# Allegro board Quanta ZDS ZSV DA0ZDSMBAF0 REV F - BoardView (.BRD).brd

Outline 275.3 x 62 mm; copper layers: TOP, IN1, GND1, IN2, SGND, SVCC, IN3, GND2, IN4, BOTTOM. Coordinates in mm from the lower left corner of the outline.
Outline path: 0,24.6 arc(0.29,25.31) 1,25.6 30.8,25.6 30.8,30.97 arc(30.95,31.33) 31.3,31.47 35.34,31.47 arc(36.03,31.44) 35.7,32.05 35.7,52.25 arc(36.03,52.86) 35.34,52.82 31.3,52.82 arc(30.95,52.97) 30.8,53.32 30.8,53.55 22.6,53.55 arc(21.89,53.84) 21.6,54.55 21.6,61 arc(21.89,61.71) 22.6,62 177.9,62 arc(178.25,61.85) 178.4,61.5 178.4,59 183.4,59 183.4,61.5 arc(183.55,61.85) 183.9,62 190.65,62 arc(191,61.85) 191.15,61.5 191.15,59 196.65,59 196.65,61.5 arc(196.8,61.85) 197.15,62 208.5,62 arc(209.21,61.71) 209.5,61 209.5,58.5 arc(209.35,58.15) 209,58 204,58 arc(203.65,57.85) 203.5,57.5 203.5,56.7 arc(203.65,56.35) 204,56.2 209,56.2 arc(209.35,56.05) 209.5,55.7 209.5,53.52 arc(209.35,53.17) 209,53.02 205.81,53.02 arc(205.13,53.31) 205.41,52.62 205.41,32.07 arc(205.13,31.39) 205.81,31.67 209,31.67 arc(209.35,31.53) 209.5,31.17 209.5,30.8 246.9,30.8 246.9,36 arc(247.49,37.41) 248.9,38 255.9,38 255.9,41 arc(256.19,41.71) 256.9,42 264.4,42 264.4,45.5 arc(264.69,46.21) 265.4,46.5 271.4,46.5 arc(272.11,46.21) 272.4,45.5 272.4,40.5 274.8,40.5 arc(275.15,40.35) 275.3,40 275.3,38.47 arc(275.15,38.12) 274.8,37.98 271.55,37.98 arc(271.05,38.47) 270.55,37.98 270.55,29.02 arc(271.05,28.52) 271.55,29.02 274.8,29.02 arc(275.15,28.88) 275.3,28.52 275.3,24.47 arc(275.15,24.12) 274.8,23.97 271.55,23.97 arc(271.05,24.47) 270.55,23.97 270.55,15.02 arc(271.05,14.52) 271.55,15.02 274.8,15.02 arc(275.15,14.88) 275.3,14.52 275.3,11.55 arc(275.15,11.2) 274.8,11.05 263.45,11.05 263.45,3.95 274.8,3.95 arc(275.15,3.8) 275.3,3.45 275.3,2.6 arc(275.15,2.25) 274.8,2.1 272.5,2.1 271,1.1 271,0.5 arc(270.85,0.15) 270.5,0 269.28,0 arc(268.98,0.1) 268.8,0.36 arc(267.6,1.25) 266.4,0.36 arc(266.22,0.1) 265.92,0 231.25,0 arc(230.9,0.15) 230.75,0.5 230.75,8.51 223.55,8.51 223.55,7.75 arc(223.4,7.4) 223.05,7.25 217.8,7.25 217.8,2 223.05,2 arc(223.4,1.85) 223.55,1.5 223.55,0.5 arc(223.4,0.15) 223.05,0 129.57,0 arc(128.86,0.29) 128.57,1 128.57,3 106.57,3 105.72,2.15 arc(105.55,2.04) 105.36,2 89.57,2 arc(88.86,2.29) 88.57,3 88.57,3.15 87.07,3.15 arc(86.72,3.3) 86.57,3.65 86.57,9.1 71.32,9.1 71.32,3.65 arc(71.17,3.3) 70.82,3.15 69.32,3.15 69.32,1 arc(69.03,0.29) 68.32,0 47.35,0 arc(46.64,0.29) 46.35,1 46.35,3 15.15,3 15.15,1 arc(14.86,0.29) 14.15,0 1,0 arc(0.29,0.29) 0,1 0,2.05 arc(0.15,2.4) 0.5,2.55 5.95,2.55 5.95,7.8 0.5,7.8 arc(0.15,7.95) 0,8.3 0,24.6

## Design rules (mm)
constraint set DEFAULT: min track width 0.117
net group DFP-S3(3.5: nets M0_A_DQSN0 M0_A_DQSN1 M0_A_DQSN2 M0_A_DQSN3 M0_A_DQSN4 M0_A_DQSN5 M0_A_DQSN6 M0_A_DQSN7 M0_A_DQSP0 M0_A_DQSP1 M0_A_DQSP2 M0_A_DQSP3 M0_A_DQSP4 M0_A_DQSP5 M0_A_DQSP6 M0_A_DQSP7 M1_A_DQSN0 M1_A_DQSN1 M1_A_DQSN2 M1_A_DQSN3 M1_A_DQSN4 M1_A_DQSN5 M1_A_DQSN6 M1_A_DQSN7 M1_A_DQSP0 M1_A_DQSP1 M1_A_DQSP2 M1_A_DQSP3 M1_A_DQSP4 M1_A_DQSP5 M1_A_DQSP6 M1_A_DQSP7
net group DFP-S6.5(3.5: nets M0_A_CLKN0 M0_A_CLKN1 M0_A_CLKP0 M0_A_CLKP1 M1_A_CLKN0 M1_A_CLKN1 M1_A_CLKP0 M1_A_CLKP1
net group DFP-S7.2(4.2: nets AUXN AUXP CLK_PCIE_WLANN CLK_PCIE_WLANP DDI1_AUXN DDI1_AUXP DDI1_TXN0 DDI1_TXN1 DDI1_TXN2 DDI1_TXN3 DDI1_TXP0 DDI1_TXP1 DDI1_TXP2 DDI1_TXP3 EDP_AUXN EDP_AUXN_C EDP_AUXP EDP_AUXP_C EDP_TXN0 EDP_TXN0_C EDP_TXN1 EDP_TXN1_C EDP_TXP0 EDP_TXP0_C EDP_TXP1 EDP_TXP1_C ML0N ML0P ML1N ML1P ML2N ML2P ML3N ML3P SATA_RXN SATA_RXN_C SATA_RXP SATA_RXP_C SATA_TXN SATA_TXN_C SATA_TXP SATA_TXP_C SSRXN SSRXP SSTXN SSTXP TYPEC1_SBU1 TYPEC1_SBU2 USB3_RXN2 USB3_RXN2_B1- USB3_RXN2_C1- USB3_RXN2_RE_C2 USB3_RXN3 USB3_RXP2 USB3_RXP2_B1+ USB3_RXP2_C1+ USB3_RXP2_RE_C2 USB3_RXP3 USB3_TXN2 USB3_TXN2_B0- USB3_TXN2_B0-_R USB3_TXN2_C0- USB3_TXN2_C0-_R USB3_TXN2_RE_C2 USB3_TXN3 USB3_TXP2 USB3_TXP2_B0+ USB3_TXP2_B0+_R USB3_TXP2_C0+ USB3_TXP2_C0+_R USB3_TXP2_RE_C2 USB3_TXP3 USBP1+_POA USBP1+_POA_R USBP1+_POA_R2 USBP1+_POA_R3 USBP1+_POA_U USBP1-_POA USBP1-_POA_R USBP1-_POA_R2 USBP1-_POA_R3 USBP1-_POA_U USBP2+ USBP2- USBP3+ USBP3- USBP4+ USBP4+_L_13 USBP4- USBP4-_L_13 USBP5+ USBP5+_L USBP5- USBP5-_L USBP6+ USBP6- WLAN_PCIE_RXN9 WLAN_PCIE_RXP9 WLAN_PCIE_TXN9 WLAN_PCIE_TXN9_C WLAN_PCIE_TXP9 WLAN_PCIE_TXP9_C
net group DFP-S7.5(6: nets TX1N TX1P TX2N TX2P TYPEC2_RX1N TYPEC2_RX1P TYPEC2_RX2N TYPEC2_RX2P TYPEC2_TX1N_C TYPEC2_TX1P_C TYPEC2_TX2N_C TYPEC2_TX2P_C
net group W4.3(2.8: nets EC_CE# EC_MISO EC_MOSI EC_SCK PCH_SPI_CLK SPI_CLK SPI_CS# SPI_IO2 SPI_IO3 SPI_SI SPI_SO
net group W4.6(2.8: nets ALERT# CPU_SVID_ALERT# PECI_R SCLK SDIO VCORE_SVID_ALERT# VCORE_SVID_CLK VCORE_SVID_DATA
net group W4.6(2.8: nets A_LAD0_R A_LAD1_R A_LAD2_R A_LAD3_R ACZ_SDIN ACZ_SDIN0 ACZ_SDOUT_AUDIO ACZ_SPK ACZ_SYNC_AUDIO ALL_SYS_PWRGD ALL_SYS_PWRGD_R BEEP_1 CATERR# CBN CBP CCG_I2C_SCL_D CCG_I2C_SDA_D CLK_LPC_KBC CLK_LPC_KBC_R CLKRUN# CPU_THRMTRIP# DMIC_CLK_13 DMIC_CLK_R DMIC_DAT_13 DMIC_DAT_14 DMIC_DAT_R DNBSWON# DPWROK_R EC_PECI EC_PWROK EC_RCIN# EC_RSMRST# EC_SMB1_CLK EC_SMB1_DATA EC_SYS_PWROK EC_WRST EDP_TX_PWM H_PROCHOT#_CPU H_PROCHOT#_EC I2C0_SCL I2C0_SDA I2C1_SCL I2C1_SDA I2C_TP_SCL_R I2C_TP_SDA_R IMVP_PWRGD IMVP_PWRGD_Q LAD0 LAD1 LAD2 LAD3 LFRAME# MASTER_SCL MASTER_SDA MBCLK MBDATA N16995392 NBSWON# PCBEEP PCH_MBCLK0 PCH_MBDAT0 PCH_PCIE_WAKE# PCH_PWRBTN# PCH_PWROK PCH_PWROK_R PCH_RSMRST# PM_NBSWON# PMIC_MBCLK PMIC_MBSDA RTC_RST# RTC_X1 RTC_X2 SLP_S0# SLP_S3# SLP_S4# SLP_SUS#_CPU SMCLK0 SMCLK4_HUB SMDAT0 SMDAT4_HUB SML0ALERT# SML1ALERT# SOC_DPST_PWM SOC_EDP_BLON SOC_EDP_ENVDD SRTC_RST# SUSCLK SUSCLK_R SUSCLK_WLAN SYS_PWROK SYS_PWROK_R THRMTRIP# TPCLK TPCLK_C TPDAT TPDAT_C TYPEC1_CCG1_VBUS_C_CTRL TYPEC1_CCG1_VBUS_DISCHARGE TYPEC1_CCG1_VBUS_P_CTRL TYPEC2_CCG4_VBUS_C_CTRL TYPEC2_CCG4_VBUS_DISCHARGE TYPEC2_CCG4_VBUS_P_CTRL UART2_RXD UART2_TXD VCCST_PWRGD VCCST_PWRGD_R VR_HOT# WLAN_RST# WRST#_8350 XCLK_BIASREF XDP_BPM0 XDP_BPM1 XTAL24_IN XTAL24_OUT
net group W5-T1234B: nets H_THRMDA H_THRMDA2 H_THRMDC H_THRMDC2
net group W5.8(3.5: nets M0_A_A0 M0_A_A1 M0_A_A3 M0_A_A4 M0_A_A5 M0_A_A6 M0_A_A7 M0_A_A8 M0_A_DQ0 M0_A_DQ1 M0_A_DQ2 M0_A_DQ3 M0_A_DQ4 M0_A_DQ5 M0_A_DQ6 M0_A_DQ7 M0_A_DQ8 M0_A_DQ9 M0_A_DQ10 M0_A_DQ11 M0_A_DQ12 M0_A_DQ13 M0_A_DQ14 M0_A_DQ15 M0_A_DQ16 M0_A_DQ17 M0_A_DQ18 M0_A_DQ19 M0_A_DQ20 M0_A_DQ21 M0_A_DQ22 M0_A_DQ23 M0_A_DQ24 M0_A_DQ25 M0_A_DQ26 M0_A_DQ27 M0_A_DQ28 M0_A_DQ29 M0_A_DQ30 M0_A_DQ31 M0_A_DQ32 M0_A_DQ33 M0_A_DQ34 M0_A_DQ35 M0_A_DQ36 M0_A_DQ37 M0_A_DQ38 M0_A_DQ39 M0_A_DQ40 M0_A_DQ41 M0_A_DQ42 M0_A_DQ43 M0_A_DQ44 M0_A_DQ45 M0_A_DQ46 M0_A_DQ47 M0_A_DQ48 M0_A_DQ49 M0_A_DQ50 M0_A_DQ51 M0_A_DQ52 M0_A_DQ53 M0_A_DQ54 M0_A_DQ55 M0_A_DQ56 M0_A_DQ57 M0_A_DQ58 M0_A_DQ59 M0_A_DQ60 M0_A_DQ61 M0_A_DQ62 M0_A_DQ63 M0_B_A3 M0_B_A9 M1_A_A0 M1_A_A1 M1_A_A2 M1_A_A3 M1_A_A4 M1_A_A5 M1_A_A6 M1_A_A7 M1_A_A8 M1_A_A9 M1_A_DQ0 M1_A_DQ1 M1_A_DQ2 M1_A_DQ3 M1_A_DQ4 M1_A_DQ5 M1_A_DQ6 M1_A_DQ7 M1_A_DQ8 M1_A_DQ9 M1_A_DQ10 M1_A_DQ11 M1_A_DQ12 M1_A_DQ13 M1_A_DQ14 M1_A_DQ15 M1_A_DQ16 M1_A_DQ17 M1_A_DQ18 M1_A_DQ19 M1_A_DQ20 M1_A_DQ21 M1_A_DQ22 M1_A_DQ23 M1_A_DQ24 M1_A_DQ25 M1_A_DQ26 M1_A_DQ27 M1_A_DQ28 M1_A_DQ29 M1_A_DQ30 M1_A_DQ31 M1_A_DQ32 M1_A_DQ33 M1_A_DQ34 M1_A_DQ35 M1_A_DQ36 M1_A_DQ37 M1_A_DQ38 M1_A_DQ39 M1_A_DQ40 M1_A_DQ41 M1_A_DQ42 M1_A_DQ43 M1_A_DQ44 M1_A_DQ45 M1_A_DQ46 M1_A_DQ47 M1_A_DQ48 M1_A_DQ49 M1_A_DQ50 M1_A_DQ51 M1_A_DQ52 M1_A_DQ53 M1_A_DQ54 M1_A_DQ55 M1_A_DQ56 M1_A_DQ57 M1_A_DQ58 M1_A_DQ59 M1_A_DQ60 M1_A_DQ61 M1_A_DQ62 M1_A_DQ63 M1_B_A0 M1_B_A1 M1_B_A2 M1_B_A3 M1_B_A4 M1_B_A5 M1_B_A6 M1_B_A7 M1_B_A8 M1_B_A9
net group W5.8(3.5: nets M0_A_ODT M0_CKE0 M0_CKE1 M0_CS0_N M0_CS1_N M1_A_ODT M1_CKE0 M1_CKE1 M1_CS0_N M1_CS1_N
net group W10-T1234B: nets HP-L2 HP-L3 HP-R2 HP-R3 HP_JD# MIC2-VREFO SENSEA
net group W12-T1234B: nets +1.5VA +3V_RTC +3V_TP_CLICK +5VA +AZA_VDD +VCCAPLL_1P0 +VCCPDSW_3P3 CFG_RCOMP CSI2_COMP DVDD_IO EDP_RCOMP EMMC_COMP LDO3V LDO5V PCIE_RCOMPN PCIE_RCOMPP SD_RCOMP SM_RCOMP_0 SM_RCOMP_1 SM_RCOMP_2 USB_BIAS VDD_V3P3A_RTC VSTBY_FSPI_R
net group W15-T1234B: nets +3V_EC_VCC +3V_POA_R +POA_PWR TYPEC1_CCG1_CC1 TYPEC1_CCG1_CC2 TYPEC2_CCG1_CC1 TYPEC2_CCG1_CC2 VCONN_5V_P1 VCONN_5V_P2
net group W20-T1234B: nets +3V_TS +5VS5_PD +SMDDR_VREF_CA +SMDDR_VREF_DQA +SMDDR_VREF_DQB +SMDDR_VTERM +V3.3S_SEN +VDDD_SUPPLY L_SPK+ L_SPK- R_SPK+ R_SPK- SLEEVE_R SM_VREF_CA SM_VREF_DQ0 SM_VREF_DQ1 V10_V1.2U_AE27 VCCPLL_OC VCCSA_DDR
net group W40-T1234B: nets +3V_PANEL_CONN +VIN_PANEL PVDD RING2 RING2_R SLEEVE

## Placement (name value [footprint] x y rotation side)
BAT1  3808k-f10n-23l  [50277-01001-V01-10P-L]  78.94 5.31 180 bottom
C1  0.1u/10v_2  [C0201]  41.57 42.76 270 top
C2  *0.1u/10v_2  [C0201]  101.01 58.12 0 top
C3  *33p/50v_2  [C0201]  45.97 49.64 90 top
C4  *0.1u/10v_2  [C0201]  102.97 50.5 0 top
C4A1  10u/10v_4  [C0402]  155.95 42.61 0 bottom
C4A2  *10u/10v_4  [C0402]  133.27 16.88 0 bottom
C4A3  10u/10v_4  [C0402]  133.27 15.48 0 bottom
C4A4  10u/10v_4  [C0402]  148.58 11.28 180 bottom
C4A5  10u/10v_4  [C0402]  150.49 11.28 0 bottom
C5  0.1u/16v_4  [C0402]  199.13 50.56 0 top
C5L1  1u/6.3v_4  [C0402]  155.88 34.38 180 bottom
C5L2  1u/6.3v_4  [C0402]  155.85 31.96 180 bottom
C5L3  1u/6.3v_4  [C0402]  155.8 30.9 180 bottom
C5L4  1u/6.3v_4  [C0402]  133.17 19.67 180 bottom
C5L5  1u/6.3v_4  [C0402]  114.6 11.97 90 bottom
C6  0.1u/16v_4  [C0402]  199.13 49.55 0 top
C6A1  1u/6.3v_4  [C0402]  155.85 37.18 180 bottom
C6A2  0.047u/16v_4  [C0402]  138.53 36.08 0 bottom
C6A3  1u/6.3v_4  [C0402]  138.4 33.54 0 bottom
C6A4  0.047u/16v_4  [C0402]  155.86 32.97 180 bottom
C6A5  0.047u/16v_4  [C0402]  105.35 26.99 270 bottom
C6A6  10u/10v_4  [C0402]  97.15 23.38 180 bottom
C6A7  1u/6.3v_4  [C0402]  133.29 18.32 180 bottom
C6A8  1u/6.3v_4  [C0402]  155.82 17.38 180 bottom
C6A9  0.047u/16v_4  [C0402]  125.22 9.85 90 bottom
C6L1  1u/6.3v_4  [C0402]  155.85 38.19 180 bottom
C6L2  1u/6.3v_4  [C0402]  155.8 29.91 180 bottom
C6L3  1u/6.3v_4  [C0402]  97.15 19.52 0 bottom
C6L4  1u/6.3v_4  [C0402]  135.55 13.27 0 bottom
C6L5  1u/6.3v_4  [C0402]  115.64 11.97 90 bottom
C6L6  1u/6.3v_4  [C0402]  123.39 9.85 90 bottom
C6L7  0.047u/16v_4  [C0402]  124.28 9.85 90 bottom
C6L8  0.047u/16v_4  [C0402]  107.56 9.76 90 bottom
C6L9  10u/10v_4  [C0402]  121.02 9.63 270 bottom
C7  4.7u/6.3v_4  [C0402]  42.92 54.72 270 top
C7A1  1u/6.3v_4  [C0402]  144.77 11.36 0 bottom
C7A2  10u/10v_4  [C0402]  106.19 9.57 270 bottom
C7L1  10u/10v_4  [C0402]  155.9 35.7 0 bottom
C7L2  0.047u/16v_4  [C0402]  106.37 26.99 270 bottom
C7L3  10u/10v_4  [C0402]  97.15 24.8 180 bottom
C7L4  10u/10v_4  [C0402]  133.24 22.47 0 bottom
C7L5  10u/10v_4  [C0402]  133.24 20.89 0 bottom
C7L6  0.047u/16v_4  [C0402]  138.32 19.45 0 bottom
C7L7  10u/10v_4  [C0402]  155.82 19.29 0 bottom
C7L8  10u/10v_4  [C0402]  155.82 18.27 0 bottom
C7L9  1u/6.3v_4  [C0402]  155.82 16.49 180 bottom
C7L10  10u/10v_4  [C0402]  97.93 14.51 270 bottom
C7L11  10u/10v_4  [C0402]  155.82 15.6 0 bottom
C7L12  10u/10v_4  [C0402]  146.68 11.28 0 bottom
C7L13  1u/6.3v_4  [C0402]  102.03 9.64 90 bottom
C7L14  *10u/10v_4  [C0402]  118.87 9.63 270 bottom
C7L15  10u/10v_4  [C0402]  122.17 9.63 270 bottom
C7L16  10u/10v_4  [C0402]  103.19 9.54 270 bottom
C9  10u/10v_4  [C0402]  199.13 48.53 0 top
C10  27p/50v_4  [C0402]  103.3 47.82 0 top
C11  27p/50v_4  [C0402]  103.29 46.97 0 top
C12  0.1u/10v_2  [C0201]  101.31 44.69 90 top
C13  0.1u/10v_2  [C0201]  96.59 41.42 90 top
C14  *1u/6.3v_4  [C0402]  95.75 39.77 270 top
C15  1u/6.3v_4  [C0402]  97.78 39.77 90 top
C16  10u/25v_8  [C0805]  261.11 38.21 270 top
C17  10u/25v_8  [C0805]  259.07 38.21 270 top
C18  10u/25v_8  [C0805]  263.14 38.21 270 top
C19  0.1u/25v_4  [C0402]  265.68 37.7 270 top
C20  0.1u/25v_4  [C0402]  264.66 37.7 270 top
C21  2.2u/10v_4  [C0402]  41.32 36.69 0 top
C22  14@0.1u/16v_4  [C0402]  81.1 36.85 90 top
C23  2.2u/10v_4  [C0402]  41.32 35.85 0 top
C24  1u/6.3v_4  [C0402]  96.58 34.17 0 top
C25  10u/10v_4  [C0402]  41.7 34.97 0 top
C26  10u/10v_4  [C0402]  41.7 33.95 0 top
C27  18p/50v_4  [C0402]  102.81 32.01 90 top
C28  0.1u/16v_4  [C0402]  198.67 33.24 90 top
C29  0.1u/16v_4  [C0402]  199.77 33.24 90 top
C30  10u/10v_4  [C0402]  41.7 32.93 0 top
C31  14@10u/10v_4  [C0402]  87.7 32.76 180 top
C32  18p/50v_4  [C0402]  102.81 33.74 270 top
C41  10u/10v_4  [C0402]  110.56 58.15 0 bottom
C42  10u/10v_4  [C0402]  114.55 59.16 0 bottom
C43  10u/10v_4  [C0402]  153.18 57.67 180 bottom
C44  0.1u/10v_2  [C0201]  34.74 57.61 0 bottom
C45  10u/10v_4  [C0402]  114.55 58.02 0 bottom
C46  10u/10v_4  [C0402]  153.18 56.29 180 bottom
C47  *22u/6.3v_4  [C0402]  114.55 56.88 0 bottom
C48  10u/10v_4  [C0402]  153.18 54.34 180 bottom
C49  10u/10v_4  [C0402]  114.55 55.73 0 bottom
C50  10u/10v_4  [C0402]  111.4 52.99 180 bottom
C51  10u/10v_4  [C0402]  133.37 52.61 270 bottom
C52  10u/10v_4  [C0402]  135.3 52.61 270 bottom
C53  10u/10v_4  [C0402]  131.44 52.61 270 bottom
C54  10u/10v_4  [C0402]  114.55 54.59 0 bottom
C55  14@10u/10v_4  [C0402]  199.87 48.78 0 bottom
C57  10u/10v_4  [C0402]  136.75 52.36 270 bottom
C58  0.1u/10v_2  [C0201]  103.5 51.7 0 bottom
C59  10u/10v_4  [C0402]  114.04 50.12 180 bottom
C60  14@0.1u/16v_4  [C0402]  199.87 49.74 180 bottom
C61  10u/10v_4  [C0402]  114.55 53.45 0 bottom
C62  10u/10v_4  [C0402]  105.58 49.69 180 bottom
C63  10u/10v_4  [C0402]  114.55 52.31 0 bottom
C64  10u/10v_4  [C0402]  137.83 49.83 270 bottom
C65  10u/10v_4  [C0402]  139.74 49.82 270 bottom
C66  10u/10v_4  [C0402]  141.65 49.82 270 bottom
C67  14@0.1u/16v_4  [C0402]  199.28 47.25 270 bottom
C68  10u/10v_4  [C0402]  110.08 48.62 180 bottom
C69  0.1u/10v_2  [C0201]  117.82 47.93 180 bottom
C70  0.1u/10v_2  [C0201]  124.81 47.84 90 bottom
C71  47u/4v_8h095  [C0805]  169.97 47.94 270 bottom
C72  *10u/10v_4  [C0402]  123.77 47.4 270 bottom
C73  0.1u/10v_2  [C0201]  118.86 47.35 90 bottom
C74  0.1u/10v_2  [C0201]  119.83 47.35 90 bottom
C75  10u/10v_4  [C0402]  120.79 47.35 270 bottom
C76  10u/10v_4  [C0402]  121.76 47.35 270 bottom
C77  0.1u/10v_2  [C0201]  122.78 47.35 90 bottom
C78  0.1u/10v_2  [C0201]  117.57 47.07 90 bottom
C79  0.1u/10v_2  [C0201]  118.28 47.07 90 bottom
C80  47u/4v_8h095  [C0805]  182.9 46.64 270 bottom
C81  47u/4v_8h095  [C0805]  184.8 46.64 270 bottom
C82  0.1u/10v_2  [C0201]  116.71 46.64 180 bottom
C83  47u/4v_8h095  [C0805]  186.71 46.62 270 bottom
C84  0.1u/10v_2  [C0201]  110.81 46.52 270 bottom
C85  *0.1u/10v_2  [C0201]  112.26 46.36 180 bottom
C86  10u/10v_4  [C0402]  181.45 46.36 270 bottom
C87  0.1u/10v_2  [C0201]  118.41 46.31 180 bottom
C88  0.1u/10v_2  [C0201]  115.49 46.24 180 bottom
C89  *1u/6.3v_2  [C0201]  124.64 46.17 0 bottom
C90  *22u/6.3v_4  [C0402]  104.57 46.16 270 bottom
C91  *22u/6.3v_4  [C0402]  105.99 46.16 270 bottom
C92  0.1u/10v_2  [C0201]  119.4 46.11 0 bottom
C93  0.1u/10v_2  [C0201]  116.71 46.03 180 bottom
C94  1u/6.3v_2  [C0201]  107.16 45.98 180 bottom
C95  *1u/6.3v_2  [C0201]  120.34 45.85 180 bottom
C96  47u/4v_8h095  [C0805]  171.9 47.94 270 bottom
C97  0.1u/10v_2  [C0201]  118.38 45.68 180 bottom
C98  0.1u/10v_2  [C0201]  121.15 45.6 90 bottom
C99  0.1u/10v_2  [C0201]  121.76 45.6 90 bottom
C100  *0.1u/10v_2  [C0201]  122.62 45.6 90 bottom
C101  0.1u/10v_2  [C0201]  110.54 45.44 0 bottom
C102  0.1u/10v_2  [C0201]  119.32 45.42 0 bottom
C103  0.1u/10v_2  [C0201]  113.4 44.69 90 bottom
C104  0.1u/10v_2  [C0201]  107.13 45.3 0 bottom
C105  *1u/6.3v_2  [C0201]  116.35 45.3 0 bottom
C106  0.1u/10v_2  [C0201]  115.44 45.24 180 bottom
C107  *1u/6.3v_2  [C0201]  120.34 45.24 180 bottom
C108  *0.1u/10v_2  [C0201]  112.29 44.56 180 bottom
C109  0.1u/10v_2  [C0201]  199.08 45.1 180 bottom
C110  0.1u/10v_2  [C0201]  118.38 45.04 180 bottom
C111  10u/10v_4  [C0402]  191.22 45.02 180 bottom
C112  0.1u/10v_2  [C0201]  110.54 44.83 0 bottom
C113  0.1u/10v_2  [C0201]  119.32 44.71 0 bottom
C114  0.01u/50v_4  [C0402]  39.87 44.64 180 bottom
C115  0.1u/10v_2  [C0201]  120.34 44.63 0 bottom
C116  *0.1u/10v_2  [C0201]  114.37 44.61 180 bottom
C117  0.1u/10v_2  [C0201]  121.15 44.53 90 bottom
C118  0.1u/10v_2  [C0201]  121.76 44.53 90 bottom
C119  *0.1u/10v_2  [C0201]  122.62 44.53 90 bottom
C120  *1u/6.3v_2  [C0201]  116.3 44.53 0 bottom
C121  10u/10v_4  [C0402]  129 44.53 270 bottom
C122  *0.1u/10v_2  [C0201]  127.3 44.51 90 bottom
C123  1u/6.3v_2  [C0201]  123.69 44.51 270 bottom
C124  0.1u/10v_2  [C0201]  118.38 44.36 180 bottom
C125  0.1u/10v_2  [C0201]  115.26 44.36 90 bottom
C126  0.1u/10v_2  [C0201]  199.08 44.34 180 bottom
C127  0.1u/10v_2  [C0201]  117.49 44.18 0 bottom
C128  0.1u/10v_2  [C0201]  119.35 44.1 0 bottom
C129  *1u/6.3v_2  [C0201]  120.34 44.02 180 bottom
C130  10u/10v_4  [C0402]  191.23 44.01 180 bottom
C131  *0.1u/10v_2  [C0201]  113.02 43.85 0 bottom
C132  *1u/6.3v_2  [C0201]  116.3 43.85 0 bottom
C133  0.1u/10v_2  [C0201]  118.41 43.67 180 bottom
C134  0.01u/50v_4  [C0402]  39.87 43.63 180 bottom
C135  *1u/6.3v_2  [C0201]  117.4 43.54 180 bottom
C136  0.1u/10v_2  [C0201]  119.35 43.47 0 bottom
C137  0.1u/10v_2  [C0201]  121.12 43.42 90 bottom
C138  0.1u/10v_2  [C0201]  121.76 43.42 90 bottom
C139  0.1u/10v_2  [C0201]  122.62 43.42 90 bottom
C140  0.1u/10v_2  [C0201]  120.34 43.41 0 bottom
C141  *1u/6.3v_2  [C0201]  123.67 43.36 270 bottom
C142  0.1u/10v_2  [C0201]  115.06 43.16 270 bottom
C143  *1u/6.3v_2  [C0201]  116.28 43.14 0 bottom
C144  0.1u/10v_2  [C0201]  118.41 42.96 180 bottom
C145  10u/10v_4  [C0402]  191.25 42.96 180 bottom
C146  *1u/6.3v_2  [C0201]  117.4 42.93 180 bottom
C147  0.1u/10v_2  [C0201]  119.35 42.83 0 bottom
C148  *1u/6.3v_2  [C0201]  120.34 42.8 180 bottom
C149  0.01u/50v_4  [C0402]  39.87 42.74 180 bottom
C150  0.1u/10v_2  [C0201]  115.23 42.32 0 bottom
C151  0.1u/10v_2  [C0201]  117.4 42.32 0 bottom
C152  0.1u/10v_2  [C0201]  121.15 42.27 90 bottom
C153  0.1u/10v_2  [C0201]  121.76 42.27 90 bottom
C154  0.1u/10v_2  [C0201]  118.33 42.27 180 bottom
C155  0.1u/10v_2  [C0201]  107.24 42.24 180 bottom
C156  0.1u/10v_2  [C0201]  119.35 42.22 0 bottom
C157  1u/6.3v_2  [C0201]  116.22 42.2 0 bottom
C158  0.1u/10v_2  [C0201]  120.34 42.19 0 bottom
C159  0.1u/10v_2  [C0201]  112.47 42.14 0 bottom
C160  0.01u/50v_4  [C0402]  39.87 41.85 180 bottom
C161  10u/10v_4  [C0402]  123.7 41.81 90 bottom
C162  1u/6.3v_2  [C0201]  122.58 41.79 90 bottom
C163  0.1u/10v_2  [C0201]  115.16 41.69 0 bottom
C164  0.1u/10v_2  [C0201]  117.34 41.61 0 bottom
C165  0.1u/10v_2  [C0201]  118.33 41.61 180 bottom
C166  0.1u/10v_2  [C0201]  119.35 41.61 0 bottom
C167  0.1u/10v_2  [C0201]  107.24 41.58 180 bottom
C168  0.1u/10v_2  [C0201]  111.2 41.58 0 bottom
C169  *1u/6.3v_2  [C0201]  120.34 41.58 180 bottom
C170  1u/6.3v_2  [C0201]  110.31 41.56 90 bottom
C171  0.1u/10v_2  [C0201]  112.47 41.51 0 bottom
C172  *0.1u/10v_2  [C0201]  113.91 41.26 0 bottom
C173  0.1u/10v_2  [C0201]  121.15 41.16 90 bottom
C174  0.1u/10v_2  [C0201]  121.76 41.16 90 bottom
C175  10u/10v_4  [C0402]  102.61 41.06 270 bottom
C176  *22u/6.3v_4  [C0402]  103.75 41.05 270 bottom
C177  0.1u/10v_2  [C0201]  115.16 41.03 0 bottom
C178  *1u/6.3v_2  [C0201]  108.3 41.02 0 bottom
C179  0.1u/10v_2  [C0201]  117.34 41 0 bottom
C180  0.1u/10v_2  [C0201]  118.33 41 180 bottom
C181  0.1u/10v_2  [C0201]  119.35 41 0 bottom
C182  0.1u/10v_2  [C0201]  120.34 40.97 0 bottom
C183  1u/6.3v_2  [C0201]  107.23 40.88 180 bottom
C184  0.1u/10v_2  [C0201]  111.2 40.82 0 bottom
C185  10u/10v_4  [C0402]  125.8 40.7 270 bottom
C186  1u/6.3v_2  [C0201]  112.44 40.62 180 bottom
C187  *22u/6.3v_4  [C0402]  116.22 40.55 90 bottom
C188  0.1u/10v_2  [C0201]  113.91 40.49 0 bottom
C189  0.1u/10v_2  [C0201]  118.33 40.39 180 bottom
C190  0.1u/10v_2  [C0201]  119.35 40.39 0 bottom
C191  0.1u/10v_2  [C0201]  115.16 40.39 0 bottom
C192  0.1u/10v_2  [C0201]  117.35 40.39 0 bottom
C193  *1u/6.3v_2  [C0201]  120.34 40.36 180 bottom
C194  0.022u/50v_4  [C0402]  137.59 40.35 90 bottom
C195  0.1u/10v_2  [C0201]  107.23 40.16 0 bottom
C196  0.1u/10v_2  [C0201]  121.15 40.11 90 bottom
C197  *0.1u/10v_2  [C0201]  121.76 40.11 90 bottom
C198  0.1u/10v_2  [C0201]  111.2 40.11 180 bottom
C199  10u/10v_4  [C0402]  123.82 40.09 0 bottom
C200  *0.1u/10v_2  [C0201]  112.44 39.94 0 bottom
C201  0.1u/10v_2  [C0201]  113.92 39.76 0 bottom
C202  0.1u/10v_2  [C0201]  120.35 39.76 0 bottom
C203  0.1u/10v_2  [C0201]  117.36 39.76 0 bottom
C204  0.1u/10v_2  [C0201]  118.36 39.76 180 bottom
C205  0.1u/10v_2  [C0201]  119.35 39.76 0 bottom
C206  0.1u/10v_2  [C0201]  115.16 39.73 0 bottom
C207  0.1u/10v_2  [C0201]  107.24 39.47 180 bottom
C209  *10u/10v_4  [C0402]  155.85 39.26 0 bottom
C210  1u/6.3v_2  [C0201]  111.17 39.22 180 bottom
C211  1u/6.3v_2  [C0201]  112.44 39.22 180 bottom
C212  10u/10v_4  [C0402]  186.68 39.2 90 bottom
C213  0.1u/10v_2  [C0201]  120.26 39.17 0 bottom
C214  0.1u/10v_2  [C0201]  118.36 39.15 180 bottom
C215  0.1u/10v_2  [C0201]  119.27 39.15 0 bottom
C216  *0.1u/10v_2  [C0201]  121.05 38.95 90 bottom
C217  *0.1u/10v_2  [C0201]  121.66 38.95 90 bottom
C218  0.1u/10v_2  [C0201]  116.22 38.95 180 bottom
C219  *1u/6.3v_2  [C0201]  122.32 38.95 270 bottom
C221  0.1u/10v_2  [C0201]  108.93 38.74 180 bottom
C222  0.1u/10v_2  [C0201]  107.26 38.64 180 bottom
C223  1u/6.3v_2  [C0201]  112.08 38.34 270 bottom
C224  0.1u/10v_2  [C0201]  111.17 38.33 0 bottom
C225  10u/10v_4  [C0402]  131.08 38.04 90 bottom
C226  0.1u/10v_2  [C0201]  113.18 38.12 0 bottom
C227  *0.1u/10v_2  [C0201]  108.93 38.06 0 bottom
C228  47u/4v_8h095  [C0805]  167.89 47.94 270 bottom
C229  *1u/6.3v_2  [C0201]  115.09 37.96 90 bottom
C230  0.1u/10v_2  [C0201]  118.2 37.96 270 bottom
C231  *1u/6.3v_2  [C0201]  125.75 37.95 90 bottom
C232  *1u/6.3v_2  [C0201]  127.4 37.95 90 bottom
C233  10u/10v_4  [C0402]  126.59 37.95 90 bottom
C234  *1u/6.3v_2  [C0201]  115.79 37.95 90 bottom
C235  10u/10v_4  [C0402]  129.94 38.03 90 bottom
C236  1u/6.3v_2  [C0201]  116.5 37.94 90 bottom
C237  0.1u/10v_2  [C0201]  117.41 37.94 270 bottom
C238  0.1u/10v_2  [C0201]  107.26 37.88 180 bottom
C239  0.1u/10v_2  [C0201]  120.82 37.83 270 bottom
C240  0.1u/10v_2  [C0201]  121.45 37.83 270 bottom
C241  0.1u/10v_2  [C0201]  122.72 37.83 270 bottom
C242  0.1u/10v_2  [C0201]  119.5 37.83 270 bottom
C243  0.1u/10v_2  [C0201]  120.16 37.83 270 bottom
C244  0.1u/10v_2  [C0201]  122.09 37.83 270 bottom
C245  0.1u/10v_2  [C0201]  118.84 37.45 270 bottom
C246  *0.1u/10v_2  [C0201]  108.94 37.3 180 bottom
C247  *10u/10v_4  [C0402]  123.76 37.22 90 bottom
C248  *0.01u/10v_2  [C0201]  138.6 37.07 180 bottom
C249  0.1u/10v_2  [C0201]  121.78 36.94 180 bottom
C250  0.1u/10v_2  [C0201]  122.69 36.94 0 bottom
C251  0.1u/10v_2  [C0201]  115.87 36.73 270 bottom
C252  0.1u/10v_2  [C0201]  116.51 36.73 270 bottom
C253  0.1u/10v_2  [C0201]  117.12 36.73 270 bottom
C254  0.1u/10v_2  [C0201]  117.75 36.73 270 bottom
C255  0.1u/10v_2  [C0201]  121.28 36.32 0 bottom
C256  0.1u/10v_2  [C0201]  122.82 35.57 0 bottom
C257  0.1u/10v_2  [C0201]  112.85 35.25 90 bottom
C258  0.1u/10v_2  [C0201]  123.86 35.17 90 bottom
C259  22u/6.3v_4  [C0402]  49.63 33.76 0 bottom
C260  0.1u/10v_2  [C0201]  138.68 34.58 180 bottom
C261  0.1u/10v_2  [C0201]  122.17 34.3 90 bottom
C262  13@0.1u/16v_4  [C0402]  253.2 33 90 bottom
C263  *10u/10v_4  [C0402]  118.28 34.12 90 bottom
C264  0.1u/10v_2  [C0201]  114.65 33.87 270 bottom
C265  *10u/10v_4  [C0402]  120.87 33.81 90 bottom
C266  0.1u/10v_2  [C0201]  127.86 33.64 270 bottom
C267  22u/6.3v_4  [C0402]  50.54 36.61 270 bottom
C268  *10u/10v_4  [C0402]  125.39 33.18 90 bottom
C269  *0.1u/10v_2  [C0201]  108.02 33.03 0 bottom
C270  0.1u/10v_2  [C0201]  122.68 32.93 270 bottom
C271  0.1u/10v_2  [C0201]  123.49 32.93 270 bottom
C272  0.1u/10v_2  [C0201]  115.31 32.87 270 bottom
C273  0.1u/10v_2  [C0201]  120.03 32.87 270 bottom
C274  0.1u/10v_2  [C0201]  138.63 32.45 180 bottom
C275  0.1u/10v_2  [C0201]  117.42 32.27 270 bottom
C276  0.1u/10v_2  [C0201]  126.66 32.21 90 bottom
C277  *0.1u/16v_4  [C0402]  41.65 29.65 270 bottom
C278  0.1u/10v_2  [C0201]  250.95 28.18 270 bottom
C279  0.1u/10v_2  [C0201]  251.71 28.18 270 bottom
C280  0.1u/16v_4  [C0402]  255.01 26.27 90 bottom
C281  *0.1u/10v_2  [C0201]  97.81 28.79 90 bottom
C282  0.1u/16v_4  [C0402]  245.05 22.66 90 bottom
C283  *33p/50v_2  [C0201]  101.37 28.29 180 bottom
C284  0.1u/16v_4  [C0402]  196.84 18.27 180 bottom
C285  0.1u/16v_4  [C0402]  248.1 27.6 270 bottom
C286  1u/6.3v_4  [C0402]  247.16 27.6 270 bottom
C287  1u/6.3v_4  [C0402]  255.01 28.18 180 bottom
C288  *0.1u/16v_4  [C0402]  42.72 27.32 270 bottom
C289  1u/6.3v_4  [C0402]  196.84 17.25 0 bottom
C290  0.022u/50v_4  [C0402]  125.06 27.09 90 bottom
C291  *0.01u/10v_2  [C0201]  123.11 27.07 90 bottom
C292  2200p/50v_4  [C0402]  81.63 27.04 270 bottom
C293  10u/10v_4  [C0402]  199.64 17.25 180 bottom
C294  0.022u/50v_4  [C0402]  155.82 25.77 0 bottom
C295  0.1u/16v_4  [C0402]  83.1 25.03 180 bottom
C296  2200p/50v_4  [C0402]  87.8 25.01 0 bottom
C297  0.1u/16v_4  [C0402]  246.25 26.14 180 bottom
C298  0.1u/16v_4  [C0402]  255.64 24.37 180 bottom
C299  0.1u/16v_4  [C0402]  255.64 23.48 180 bottom
C300  0.022u/50v_4  [C0402]  202.43 20.43 270 bottom
C301  0.1u/16v_4  [C0402]  246.25 25.25 180 bottom
C302  *0.1u/25v_4  [C0402]  202.94 23.98 0 bottom
C303  *0.01u/50v_4  [C0402]  155.75 23.69 180 bottom
C304  0.1u/16v_4  [C0402]  36.64 23.47 0 bottom
C305  0.1u/16v_4  [C0402]  246.25 24.37 180 bottom
C306  *1000p/25v_6  [C0603]  203.07 28.68 0 bottom
C307  0.1u/16v_4  [C0402]  36.64 22.58 0 bottom
C308  0.1u/16v_4  [C0402]  34.76 22.22 0 bottom
C309  0.1u/16v_4  [C0402]  246.25 23.48 180 bottom
C310  0.1u/10v_2  [C0201]  51.23 22.11 90 bottom
C311  0.1u/10v_2  [C0201]  51.99 22.11 90 bottom
C312  22u/6.3v_6  [C0603]  97.15 21.83 0 bottom
C313  0.1u/16v_4  [C0402]  255.82 21.76 180 bottom
C314  0.1u/16v_4  [C0402]  237.13 25 90 bottom
C315  0.1u/16v_4  [C0402]  239.39 20.68 180 bottom
C316  0.1u/16v_4  [C0402]  34.76 21.34 0 bottom
C317  0.1u/16v_4  [C0402]  36.82 20.93 0 bottom
C318  0.1u/16v_4  [C0402]  231.26 26.27 180 bottom
C322  0.1u/16v_4  [C0402]  244.21 21.32 180 bottom
C323  0.1u/16v_4  [C0402]  255.82 20.74 180 bottom
C324  0.1u/10v_2  [C0201]  97.1 20.51 180 bottom
C325  0.1u/16v_4  [C0402]  36.82 20.04 0 bottom
C326  0.1u/10v_2  [C0201]  155.82 20.17 0 bottom
C327  0.1u/16v_4  [C0402]  231.26 25.38 180 bottom
C328  0.1u/16v_4  [C0402]  244.21 20.43 180 bottom
C329  0.1u/16v_4  [C0402]  236.21 25 90 bottom
C330  0.1u/10v_2  [C0201]  47.42 18.96 90 bottom
C331  0.1u/10v_2  [C0201]  48.18 18.96 90 bottom
C332  *0.1u/10v_2  [C0201]  49.04 18.96 90 bottom
C333  0.1u/16v_4  [C0402]  231.26 24.37 180 bottom
C334  0.1u/10v_2  [C0201]  43.53 18.81 90 bottom
C335  0.1u/10v_2  [C0201]  44.42 18.81 90 bottom
C336  0.1u/16v_4  [C0402]  243.71 25.38 0 bottom
C337  0.1u/16v_4  [C0402]  244.21 19.54 180 bottom
C338  2.2u/10v_4  [C0402]  256.03 18.27 180 bottom
C339  0.1u/16v_4  [C0402]  231.26 23.48 180 bottom
C340  0.1u/16v_4  [C0402]  243.71 24.49 0 bottom
C341  0.1u/16v_4  [C0402]  240.28 28.05 0 bottom
C342  0.1u/16v_4  [C0402]  247.44 17.69 270 bottom
C343  0.1u/16v_4  [C0402]  248.46 17.69 270 bottom
C344  1u/6.3v_4  [C0402]  249.47 17.69 90 bottom
C345  0.1u/16v_4  [C0402]  250.49 17.69 90 bottom
C346  0.1u/16v_4  [C0402]  251.45 17.89 270 bottom
C347  0.1u/16v_4  [C0402]  252.47 17.89 270 bottom
C348  mll@180p/50v_4  [C0402]  50.01 17.49 270 bottom
C349  mll@180p/50v_4  [C0402]  45.26 17.44 90 bottom
C350  mll@180p/50v_4  [C0402]  46.27 17.44 90 bottom
C351  0.1u/16v_4  [C0402]  244.21 18.65 180 bottom
C352  0.1u/10v_2  [C0201]  9.54 17 0 bottom
C353  10p/50v_4  [C0402]  61.79 16.81 0 bottom
C354  *10p/50v_2  [C0201]  244.09 15.81 180 bottom
C355  100p/50v_4  [C0402]  252.85 16.24 270 bottom
C356  0.1u/10v_2  [C0201]  251.25 15.86 0 bottom
C357  *10p/50v_2  [C0201]  245.21 15.81 0 bottom
C358  mll@180p/50v_4  [C0402]  8.23 15.79 0 bottom
C359  1u/6.3v_4  [C0402]  64.18 15.59 180 bottom
C360  10u/25v_6  [C0603]  36.77 15.38 0 bottom
C362  0.1u/16v_4  [C0402]  243.71 23.22 0 bottom
C364  *220p/50v_4  [C0402]  61.92 14.49 180 bottom
C365  10u/10v_4  [C0402]  249.75 14.24 180 bottom
C367  *1000p/50v_4  [C0402]  255.49 14.14 270 bottom
C368  0.1u/16v_4  [C0402]  256.43 14.14 270 bottom
C369  1000p/50v_4  [C0402]  36.77 14.13 180 bottom
C370  *22p/50v_4  [C0402]  247.19 13.88 90 bottom
C371  10u/10v_4  [C0402]  248.2 13.88 270 bottom
C372  0.1u/16v_4  [C0402]  243.71 22.33 0 bottom
C373  0.1u/16v_4  [C0402]  239.39 19.79 180 bottom
C374  0.1u/10v_2  [C0201]  249.5 13.4 0 bottom
C375  10u/10v_4  [C0402]  242.87 13.1 0 bottom
C376  *220p/50v_4  [C0402]  58.54 12.58 180 bottom
C377  14@0.1u/16v_4  [C0402]  157.42 9.23 180 bottom
C378  14@0.1u/16v_4  [C0402]  157.32 10.93 270 bottom
C379  14@0.1u/16v_4  [C0402]  158.34 12.43 0 bottom
C380  0.1u/10v_2  [C0201]  244.22 12.51 270 bottom
C381  14@0.1u/16v_4  [C0402]  155.82 11.31 180 bottom
C382  1000p/50v_4  [C0402]  234.56 12.05 180 bottom
C383  14@0.1u/16v_4  [C0402]  152.37 11.31 0 bottom
C384  10u/10v_4  [C0402]  242.87 12.13 0 bottom
C385  2.2u/10v_4  [C0402]  9.57 17.81 180 bottom
C386  2.2u/10v_4  [C0402]  20.24 11.88 90 bottom
C387  0.1u/16v_4  [C0402]  21.12 11.88 270 bottom
C388  *220p/50v_2  [C0201]  22.6 11.75 90 bottom
C389  *220p/50v_2  [C0201]  23.49 11.75 90 bottom
C390  *220p/50v_2  [C0201]  24.45 11.75 90 bottom
C391  *220p/50v_2  [C0201]  25.34 11.75 90 bottom
C392  *220p/50v_2  [C0201]  26.23 11.75 90 bottom
C393  *220p/50v_2  [C0201]  27.12 11.75 90 bottom
C394  *220p/50v_2  [C0201]  28.01 11.75 90 bottom
C395  *220p/50v_2  [C0201]  28.9 11.75 90 bottom
C396  *220p/50v_2  [C0201]  29.79 11.75 90 bottom
C397  *220p/50v_2  [C0201]  30.68 11.75 90 bottom
C398  *220p/50v_2  [C0201]  31.57 11.75 90 bottom
C399  *220p/50v_2  [C0201]  32.46 11.75 90 bottom
C400  *220p/50v_2  [C0201]  33.34 11.75 90 bottom
C401  *220p/50v_2  [C0201]  34.23 11.75 90 bottom
C402  *220p/50v_2  [C0201]  35.12 11.75 90 bottom
C403  *220p/50v_2  [C0201]  36.01 11.75 90 bottom
C404  *220p/50v_2  [C0201]  36.93 11.75 90 bottom
C405  *220p/50v_2  [C0201]  37.79 11.75 90 bottom
C406  *220p/50v_2  [C0201]  38.68 11.75 90 bottom
C407  *220p/50v_2  [C0201]  39.57 11.75 90 bottom
C408  *220p/50v_2  [C0201]  40.58 11.75 90 bottom
C409  *220p/50v_2  [C0201]  41.47 11.75 90 bottom
C410  *220p/50v_2  [C0201]  42.36 11.75 90 bottom
C411  *220p/50v_2  [C0201]  43.25 11.75 90 bottom
C412  14@1u/6.3v_4  [C0402]  155.47 12.43 0 bottom
C413  *33p/50v_2  [C0201]  63.32 11.45 0 bottom
C414  14@0.1u/16v_4  [C0402]  154.1 11.31 180 bottom
C415  0.1u/10v_2  [C0201]  243.1 10.91 180 bottom
C416  0.1u/10v_2  [C0201]  142.49 11.41 270 bottom
C417  0.1u/10v_2  [C0201]  143.38 11.41 270 bottom
C418  *220p/50v_4  [C0402]  137.05 9.63 270 bottom
C419  1000p/50v_4  [C0402]  234.89 10.53 270 bottom
C420  1000p/50v_4  [C0402]  233.55 10.28 90 bottom
C421  100p/50v_4  [C0402]  259.89 10.07 90 bottom
C423  0.1u/10v_2  [C0201]  119.88 9.63 270 bottom
C424  0.1u/10v_2  [C0201]  101.21 9.67 270 bottom
C425  22u/6.3v_6  [C0603]  117.21 9.51 90 bottom
C426  22u/6.3v_6  [C0603]  104.69 9.57 90 bottom
C428  *220p/50v_4  [C0402]  137.05 11.54 90 bottom
C429  *10u/10v_4  [C0402]  224.66 14.21 270 bottom
C430  *220p/50v_4  [C0402]  134.99 8.62 90 bottom
C431  10u/10v_4  [C0402]  239.39 8.45 0 bottom
C432  1000p/50v_4  [C0402]  234.89 8.24 270 bottom
C433  mll@180p/50v_4  [C0402]  45.97 9.79 90 bottom
C434  10u/10v_4  [C0402]  253.23 7.84 90 bottom
C436  100p/50v_4  [C0402]  259.89 7.79 90 bottom
C437  *1u/6.3v_4  [C0402]  237.1 15.73 180 bottom
C438  0.1u/10v_2  [C0201]  239.44 7.58 180 bottom
C439  *220p/50v_4  [C0402]  134.99 6.71 270 bottom
C440  0.1u/10v_2  [C0201]  242.92 7.15 180 bottom
C441  *220p/50v_4  [C0402]  58.41 7.07 180 bottom
C442  mll@180p/50v_4  [C0402]  16.16 6.91 270 bottom
C443  4.7u/6.3v_4  [C0402]  254.68 6.9 180 bottom
C444  1u/6.3v_4  [C0402]  239.06 6.72 180 bottom
C445  10u/10v_4  [C0402]  242.59 6.37 0 bottom
C446  1u/6.3v_4  [C0402]  142.71 10.4 0 bottom
C447  4.7u/6.3v_4  [C0402]  254.68 5.88 180 bottom
C451  10u/10v_4  [C0402]  242.72 5.37 180 bottom
C452  100p/50v_4  [C0402]  259.89 5.25 270 bottom
C453  14@0.1u/16v_4  [C0402]  157.22 2.98 270 bottom
C454  14@1000p/50v_4  [C0402]  162.68 12.99 270 bottom
C455  0.1u/10v_2  [C0201]  52.85 4.61 270 bottom
C456  0.1u/10v_2  [C0201]  53.66 4.61 270 bottom
C457  *10u/10v_4  [C0402]  233.57 4.69 180 bottom
C458  *0.1u/10v_2  [C0201]  54.43 4.68 270 bottom
C459  *0.1u/16v_4  [C0402]  242.11 4.49 180 bottom
C460  10u/10v_4  [C0402]  244.85 4.18 90 bottom
C461  0.1u/10v_2  [C0201]  252.39 4.1 270 bottom
C462  10u/10v_4  [C0402]  253.36 4 90 bottom
C463  1u/6.3v_2  [C0201]  245.71 3.9 90 bottom
C464  1u/6.3v_2  [C0201]  246.43 3.9 90 bottom
C466  *0.1u/16v_4  [C0402]  233.57 3.65 0 bottom
C467  14@0.1u/16v_4  [C0402]  160.06 12.48 180 bottom
C468  *10u/10v_4  [C0402]  242.11 3.47 0 bottom
C470  0.1u/16v_4  [C0402]  57.15 3.06 90 bottom
C471  100p/50v_4  [C0402]  259.89 3.09 270 bottom
C472  2.2u/10v_4  [C0402]  249.04 3.04 90 bottom
C473  10u/10v_4  [C0402]  250.49 2.71 180 bottom
C477  10u/10v_4  [C0402]  110.08 47.78 180 bottom
C478  10u/10v_4  [C0402]  114.15 43.29 90 bottom
C479  10u/10v_4  [C0402]  113.02 45.6 0 bottom
C480  10u/10v_4  [C0402]  104.87 41.05 270 bottom
C481  10u/10v_4  [C0402]  112.36 47.53 270 bottom
C482  10u/10v_4  [C0402]  114.04 49.13 180 bottom
C483  47u/4v_8h095  [C0805]  167.18 39.91 90 bottom
C484  47u/4v_8h095  [C0805]  165.25 39.91 90 bottom
C485  47u/4v_8h095  [C0805]  173.83 47.94 270 bottom
C486  47u/6.3v_8  [C0805]  173.43 48.95 180 top
C487  47u/4v_8h095  [C0805]  169.67 38.54 90 bottom
C488  47u/4v_8h095  [C0805]  165.86 47.94 270 bottom
C489  47u/6.3v_8  [C0805]  191.21 43.7 180 top
C490  47u/6.3v_8  [C0805]  190.57 48.11 270 top
C491  47u/6.3v_8  [C0805]  188.06 48.11 270 top
C703  **poa@0.1u/10v_2  [C0201]  174.8 5.42 0 bottom
C725  *1000p/50v_4  [C0402]  169.49 10.01 90 bottom
C726  **poa@2.2u/10v_4  [C0402]  171.72 13.27 90 bottom
C731  *poa@4.7u/6.3v_4  [C0402]  171.01 10.4 0 bottom
C927  **poa@1000p/50v_4  [C0402]  173.17 13.85 180 bottom
C928  *10u/10v_4  [C0402]  124.89 37.22 90 bottom
C929  *10u/10v_4  [C0402]  51.89 32.11 180 bottom
C930  *10u/10v_4  [C0402]  51.89 33.08 180 bottom
C931  0.1u/16v_4  [C0402]  197.22 23.1 270 bottom
C933  *47u/6.3v_8  [C0805]  53.08 33.36 180 top
C934  22u/6.3v_6  [C0603]  135.63 22.33 0 bottom
C935  22u/6.3v_6  [C0603]  135.63 18.14 0 bottom
C936  22u/6.3v_6  [C0603]  135.63 14.59 0 bottom
C937  22u/6.3v_6  [C0603]  135.5 35.16 270 bottom
C938  22u/6.3v_6  [C0603]  133.98 35.16 270 bottom
C939  22u/6.3v_6  [C0603]  132.45 35.16 270 bottom
C940  22u/6.3v_6  [C0603]  130.55 35.16 270 bottom
C941  390p/50v_4  [C0402]  221.23 27.92 90 bottom
C942  390p/50v_4  [C0402]  220.21 27.92 90 bottom
C943  0.1u/25v_4  [C0402]  228.09 19.03 0 bottom
C944  0.1u/25v_4  [C0402]  217.39 19.41 90 bottom
C945  0.1u/16v_4  [C0402]  218.18 27.92 90 bottom
C946  1u/6.3v_4  [C0402]  219.2 27.92 270 bottom
C947  390p/50v_4  [C0402]  218.43 15.35 90 bottom
C948  390p/50v_4  [C0402]  222.88 14.71 90 bottom
C949  1u/6.3v_4  [C0402]  228.09 21.06 0 bottom
C950  1u/6.3v_4  [C0402]  228.09 22.08 180 bottom
C951  0.1u/16v_4  [C0402]  228.09 24.11 0 bottom
C952  0.1u/16v_4  [C0402]  228.09 23.1 0 bottom
C953  0.1u/16v_4  [C0402]  217.42 17.13 90 bottom
C954  0.1u/16v_4  [C0402]  199.26 9 180 bottom
C955  0.022u/50v_4  [C0402]  198.11 3.41 180 bottom
C956  0.1u/16v_4  [C0402]  195.95 8.36 90 bottom
C957  1u/6.3v_4  [C0402]  194.94 8.36 270 bottom
C958  10u/10v_4  [C0402]  194.94 5.95 90 bottom
C959  *0.1u/25v_4  [C0402]  202.18 3.66 180 bottom
C960  0.1u/25v_4  [C0402]  264.79 22.97 90 top
C961  0.1u/25v_4  [C0402]  265.8 22.97 90 top
C962  10u/25v_8  [C0805]  263.26 22.97 90 top
C963  10u/25v_8  [C0805]  265.3 26.65 270 top
C964  10u/25v_8  [C0805]  263.26 26.52 270 top
C965  *1000p/25v_6  [C0603]  207.13 4.17 0 bottom
CL1_CL1  *pad  [FUNTP-C50-79-2P]  97.1 36.87 180 top
CL1_CL2  *pad  [FUNTP-C50-79-2P]  65.91 4.31 180 bottom
CN1  nase0-a6701-1s14  [NGFF-NASE0-A6701-1S14-75P-KE]  203.57 42.35 90 top
CN2  80149-3521  [NGFF-80149-3521-75P-KB]  37.53 42.15 270 top
CN3  ausb0295-p001a  [UB31-DX07B024XJ1AR1000-24P-SMT]  268.55 33.5 90 top
CN5  2sj3175-000111f  [AUDIO-AJ3F7D-Y150-412-6P]  270.65 7.5 90 top
CN6  14@4251k-f08n-00l  [50376-00801-V01-8P-L]  199 52.6 0 bottom
CN7  13@4251k-f08n-00l  [50376-00801-V01-8P-L]  250.29 34.1 90 bottom
CN8  4251k-f06n-00l  [4251K-F06N-00L-6P-L]  1.6 20.5 90 bottom
CN9  51569-03201-001  [51569-03201-001-32P-L]  23.8 17.7 0 bottom
CN10  14@132a06-000022-m1-r  [50521-0060N-V01-6P-L]  2.95 13.5 90 bottom
CN11  50699-02601-v02  [50699-02601-AT1-26P-L]  31.25 5.8 180 bottom
CN12  132a06-000022-a2-r  [50521-00641-V01-6P-L]  141.85 5.45 180 bottom
CN13  50277-00201-v01  [50277-00201-001-2P-L]  2.17 5.18 90 bottom
CN14  50277-00201-v01  [50277-00201-001-2P-L]  221.57 4.62 270 bottom
CN16  *6702b08-0100r0-g2-r  [50521-00801-V01-8P-L]  160.7 5.65 180 bottom
CN17  *poa@6702b08-0100r0-g2-r  [50521-00801-V01-8P-L]  167.6 5.65 180 bottom
CN18  ausb0295-p001a  [UB31-DX07B024XJ1AR1000-24P-SMT]  268.55 19.5 90 top
D1  mll@az5725-01f.r7g  [C0402]  44.57 52.18 180 top
D2  *vport_6  [R0603]  44.32 56.12 90 top
D3  rb500v-40_100ma  [DSM]  73.35 32.98 180 top
D4  mll@d24v0l1b2lps-7b  [D-1X0_6-D24V0L1B2LPS]  258.95 35.54 180 top
D6  *14@mlvs0402k11  [C0402]  180.64 55.16 90 bottom
D7  *14@mlvs0402k11  [C0402]  181.66 55.16 90 bottom
D8  *14@mlvs0402k11  [C0402]  183.67 55.14 90 bottom
D9  *13@mlvs0402k11  [C0402]  187.47 55.13 90 bottom
D10  *13@mlvs0402k11  [C0402]  188.44 55.13 90 bottom
D11  *13@mlvs0402k11  [C0402]  191.26 55.13 90 bottom
D12  *13@mlvs0402k11  [C0402]  193.19 55.13 90 bottom
D13  *14@mlvs0402k11  [C0402]  185.58 55.13 90 bottom
D14  az5325-01f.r7gr  [R0402]  194.3 52.18 90 bottom
D15  az5325-01f.r7gr  [R0402]  194.3 54.06 270 bottom
D16  *pesd5v0f1bl  [R0402]  5.38 20.6 180 bottom
D17  *pesd5v0f1bl  [R0402]  5.36 19.23 180 bottom
D18  1n4148ws_200ma  [DSM]  39.01 16.04 90 bottom
D19  1n4148ws_200ma  [DSM]  239.06 14.26 90 bottom
D20  1n4148ws_200ma  [DSM]  240.96 14.26 90 bottom
D21  14@rb500v-40_100ma  [DSM]  158.66 15.15 270 bottom
D22  rb500v-40_100ma  [DSM]  62.2 13.12 0 bottom
D23  *az5725-01f.r7g  [C0402]  255.32 11.85 270 bottom
D24  *esd  [ESD-69X31]  256.46 11.85 90 bottom
D25  *esd  [ESD-69X31]  213.99 2.62 180 bottom
D26  *esd  [ESD-69X31]  213.99 3.56 180 bottom
D27  *esd  [ESD-69X31]  138.07 9.63 270 bottom
D28  mll@az5725-01f.r7g  [C0402]  260.9 10.07 90 bottom
D29  *esd  [ESD-69X31]  138.07 11.54 90 bottom
D30  *esd  [ESD-69X31]  136.01 8.62 90 bottom
D31  mll@az5725-01f.r7g  [C0402]  260.9 7.79 90 bottom
D32  *esd  [ESD-69X31]  136.01 6.71 270 bottom
D33  *esd  [ESD-69X31]  10.56 5.8 0 bottom
D34  *esd  [ESD-69X31]  260.9 5.12 90 bottom
D35  *rb500v-40_100ma  [DSM]  234.05 15.73 0 bottom
D36  rb500v-40_100ma  [DSM]  234.05 13.82 0 bottom
D37  *esd  [ESD-69X31]  10.56 4.55 0 bottom
D38  *esd  [ESD-69X31]  260.9 3.09 90 bottom
D39  rb500v-40_100ma  [DSM]  62.1 28.05 0 bottom
D49  **poa@d5v0x1b2lp-7b  [C0402]  173.73 9.23 0 bottom
D50  **poa@d5v0x1b2lp-7b  [C0402]  172 9.23 180 bottom
D51  mll@d24v0l1b2lps-7b  [D-1X0_6-D24V0L1B2LPS]  265.93 24.49 0 top
EC1  68p/25v_2  [C0201]  70.15 57.24 270 top
EC2  0.47u/25v_2  [C0201]  70.83 57.24 270 top
EC3  2200p/25v_2  [C0201]  71.54 57.24 270 top
EC4  2200p/25v_2  [C0201]  62.07 48.96 90 bottom
EC5  68p/25v_2  [C0201]  62.88 48.96 90 bottom
EC6  0.47u/25v_2  [C0201]  63.62 48.96 90 bottom
EC7  0.1u/10v_2  [C0201]  111.53 46.51 270 bottom
EC8  0.1u/10v_2  [C0201]  113.02 43.03 0 bottom
EC9  68p/25v_2  [C0201]  82.57 20.8 180 bottom
EC10  2200p/25v_2  [C0201]  82.57 20.04 180 bottom
EC11  0.47u/25v_2  [C0201]  82.57 19.28 180 bottom
EL1  sby100505t-101y-n_500ma  [R0402]  105.63 48.55 0 bottom
HOLE1  h-tc276bc236d197p2  [H-TC276BC236D197P2]  62.8 56.8 0 top
HOLE2  h-tc315bc236d197p2  [H-TC315BC236D197P2]  169 56.8 0 top
HOLE3  *h-c197d98p2bb  [H-C197D98P2BB]  92.9 56.5 0 top
HOLE4  *h-o79x118d79x118n  [H-O79X118D79X118N]  86.9 56.5 90 top
HOLE5  h-tc256bc177d177p2  [H-TC256BC177D177P2]  146.1 53.35 0 top
HOLE6  *h-c79d79n  [H-C79D79N]  270.6 43.8 0 top
HOLE7  *h-tc217ibc197d98p2bb  [H-TC217IBC197D98P2BB]  45.9 37.5 0 top
HOLE8  *h-tc217ibc197d98p2bb  [H-TC217IBC197D98P2BB]  160.9 37.5 0 top
HOLE9  h-tc256bc177d177p2  [H-TC256BC177D177P2]  90.1 37.35 0 top
HOLE10  *h-t99i-2bb  [H-T99I-2BB]  263.4 17 0 top
HOLE11  *h-tc217ibc197d98p2bb  [H-TC217IBC197D98P2BB]  267.6 0 0 top
HOLE12  *h-t99i-1  [H-T99I-1]  266.9 42.3 180 bottom
HOLE13  h-c51d51n  [H-C51D51N]  140.6 53.35 0 top
HOLE14  h-c51d51n  [H-C51D51N]  87.07 47.6 0 top
L11  blm15ag121sn1d_500ma  [R0402]  240.84 6.72 0 bottom
L12  hcb1608kf-600t30_3a  [R0603]  233.73 6.52 270 bottom
L13  hcb2012kf-220t60_6a  [R0805]  236.39 6.34 180 bottom
L14  14@hcb1005kf-181t15_1.5a  [R0402]  164.18 12.61 180 bottom
L15  14@hcb1005kf-181t15_1.5a  [R0402]  164.18 13.57 180 bottom
LED1  13@ltst-c191tbkt  [LEDLTST-C190TGKT]  190 60.71 90 top
LED2  13@ltst-c191tbkt  [LEDLTST-C190TGKT]  199.4 60.7 90 top
LED3  13@ltst-c191kfkt  [LEDLTST-C190TGKT]  188.71 60.7 90 top
LED4  13@ltst-c191kfkt  [LEDLTST-C190TGKT]  198.1 60.7 90 top
LED5  14@ltst-s326tbkfkt-q  [LEDLTST-S326KGJRKT-3P-SMT]  175.89 60.51 0 top
LED6  14@ltst-s326tbkfkt-q  [LEDLTST-S326KGJRKT-3P-SMT]  185.9 60.49 0 top
MR1  yb8251st23  [SOT23_123-2_8-1_9]  41.92 52.86 270 top
NOREF  -  []  36.42 10.76 0 top
NOREF#2  -  []  147.44 -21.52 0 top
NOREF#3  -  []  -21.77 -32.04 0 top
NOREF#4  -  []  138.37 34.7 0 top
NOREF#5  -  [unnamed#2]  175.46 55.61 0 top
NOREF#6  -  [unnamed#2]  11.98 3.18 0 top
NOREF#7  -  [unnamed#2]  258.85 15.22 0 top
NOREF#8  -  [unnamed#2]  73.58 58.86 180 bottom
NOREF#9  -  [unnamed#2]  259.84 38.46 180 bottom
NOREF#10  -  []  26.41 57.79 0 bottom
NOREF#11  -  [unnamed#2]  10.66 22.03 180 bottom
NOREF#12  -  []  55.75 52.94 180 bottom
PC1  0.1u/10v_2  [C0201]  82.21 59.5 90 top
PC2  1000p/50v_2  [C0201]  82.93 59.5 90 top
PC3  1000p/50v_2  [C0201]  83.66 59.5 90 top
PC4  0.1u/10v_2  [C0201]  84.37 59.5 90 top
PC5  22u/6.3v_6  [C0603]  79.29 59.32 180 top
PC6  10u/10v_4  [C0402]  89.02 59.29 0 top
PC7  22u/6.3v_6  [C0603]  48.48 58.16 270 top
PC8  22u/6.3v_6  [C0603]  49.86 58.16 270 top
PC9  22u/6.3v_6  [C0603]  51.18 58.16 270 top
PC10  22u/6.3v_6  [C0603]  52.47 58.16 270 top
PC11  47u/6.3v_6  [C0603]  47.11 58.13 270 top
PC12  22u/6.3v_6  [C0603]  79.28 57.91 180 top
PC13  22u/6.3v_6  [C0603]  79.28 56.56 180 top
PC14  22u/6.3v_6  [C0603]  79.29 55.11 180 top
PC15  22u/6.3v_6  [C0603]  153.03 55.11 180 top
PC16  2.2u/10v_4  [C0402]  155.27 54.64 90 top
PC17  10u/25v_6  [C0603]  70.23 54.6 0 top
PC18  0.22u/25v_6x  [C0603]  159.53 53.69 90 top
PC19  22u/6.3v_6  [C0603]  153.03 53.63 180 top
PC20  0.1u/10v_2  [C0201]  85.44 53.48 0 top
PC21  10u/25v_6  [C0603]  70.22 53.15 0 top
PC22  10u/25v_6  [C0603]  59.49 51.92 270 top
PC23  10u/25v_6  [C0603]  58.04 51.92 270 top
PC24  0.1u/10v_2  [C0201]  92.15 51.7 180 top
PC25  10u/10v_4  [C0402]  95.91 51.58 270 top
PC26  1u/6.3v_2  [C0201]  68.9 51.42 90 top
PC27  0.47u/25v_2  [C0201]  71.34 51.42 90 top
PC28  0.1u/10v_2  [C0201]  88.79 50.99 90 top
PC29  1000p/50v_2  [C0201]  94.66 50.66 0 top
PC30  47u/6.3v_6  [C0603]  80.08 50.24 270 top
PC31  47u/6.3v_6  [C0603]  81.47 50.24 270 top
PC32  22u/6.3v_6  [C0603]  82.87 50.24 270 top
PC33  47u/6.3v_6  [C0603]  84.27 50.24 270 top
PC34  22u/6.3v_6  [C0603]  78.02 50.25 270 top
PC35  1000p/50v_2  [C0201]  94.66 49.95 0 top
PC36  0.1u/10v_2  [C0201]  94.66 49.27 0 top
PC37  10u/25v_6  [C0603]  162.96 50.3 180 top
PC38  2200p/50v_4  [C0402]  56.6 46.5 0 top
PC39  0.1u/25v_4  [C0402]  54.45 46.5 180 top
PC40  2200p/50v_4  [C0402]  162.76 49.08 0 top
PC41  0.1u/10v_2  [C0201]  91.08 47.34 0 top
PC42  10u/25v_6  [C0603]  54.34 45.25 0 top
PC43  10u/10v_4  [C0402]  77.69 46.8 270 top
PC44  0.1u/25v_4  [C0402]  162.76 47.94 180 top
PC45  22u/6.3v_6  [C0603]  94.71 46.5 0 top
PC46  0.1u/25v_4  [C0402]  156.64 45.17 270 top
PC47  1u/6.3v_2  [C0201]  63.21 45.52 0 top
PC48  0.1u/25v_4  [C0402]  162.73 46.51 180 top
PC49  0.1u/10v_2  [C0201]  91.56 45.51 0 top
PC50  0.1u/10v_2  [C0201]  86.79 45.28 270 top
PC51  *0.1u/10v_2  [C0201]  51.43 43.03 180 top
PC52  *22u/6.3v_6  [C0603]  76.73 44.97 180 top
PC53  1u/6.3v_2  [C0201]  61.41 44.84 90 top
PC54  2.2u/10v_4  [C0402]  62.1 43.44 270 top
PC55  1u/6.3v_2  [C0201]  57.65 41.89 90 top
PC56  *22u/6.3v_6  [C0603]  91.74 43.93 0 top
PC57  1u/25v_4  [C0402]  59.43 43.8 90 top
PC58  0.1u/10v_2  [C0201]  87.42 42.23 270 top
PC59  1000p/50v_2  [C0201]  88.29 42.23 270 top
PC60  1000p/50v_2  [C0201]  89.15 42.23 270 top
PC61  0.1u/10v_2  [C0201]  90.01 42.07 270 top
PC62  10u/10v_4  [C0402]  85.01 40.63 270 top
PC63  1u/6.3v_2  [C0201]  72.61 39.13 90 top
PC64  4.7u/6.3v_4  [C0402]  66.52 38.78 270 top
PC65  10u/10v_4  [C0402]  70.45 38.42 270 top
PC66  22u/6.3v_6  [C0603]  53.95 36.02 90 top
PC67  22u/6.3v_6  [C0603]  52.68 36.02 90 top
PC68  10u/25v_6  [C0603]  76.85 37.71 90 top
PC69  10u/25v_6  [C0603]  78.33 37.71 90 top
PC70  0.1u/25v_4  [C0402]  79.65 37.68 90 top
PC71  10u/25v_6  [C0603]  182.93 34.51 0 top
PC72  10u/25v_6  [C0603]  172.97 34.41 180 top
PC73  22u/6.3v_6  [C0603]  68.55 33.72 90 top
PC74  22u/6.3v_6  [C0603]  69.95 33.72 90 top
PC75  47u/6.3v_6  [C0603]  56.94 33.66 90 top
PC76  47u/6.3v_6  [C0603]  55.47 33.64 90 top
PC77  10u/25v_6  [C0603]  182.9 33.04 0 top
PC78  10u/25v_6  [C0603]  172.89 33.01 180 top
PC79  0.1u/10v_2  [C0201]  164.29 32.95 0 top
PC80  10u/10v_4  [C0402]  83.69 59.01 270 bottom
PC81  1u/25v_4  [C0402]  71.74 56.67 0 bottom
PC82  *0.1u/10v_2  [C0201]  81.95 55.51 90 bottom
PC83  0.1u/10v_2  [C0201]  82.66 55.51 270 bottom
PC84  *0.1u/10v_2  [C0201]  83.37 55.51 90 bottom
PC85  0.1u/10v_2  [C0201]  84.17 55.49 90 bottom
PC86  0.1u/25v_4  [C0402]  74.06 54.85 270 bottom
PC87  2200p/50v_4  [C0402]  75.2 52.95 90 bottom
PC88  2200p/50v_4  [C0402]  156.75 51.42 90 bottom
PC89  *0.1u/10v_2  [C0201]  90.42 50.05 0 bottom
PC90  0.1u/10v_2  [C0201]  90.42 49.34 180 bottom
PC91  *0.1u/10v_2  [C0201]  90.42 48.66 0 bottom
PC92  0.1u/25v_4  [C0402]  61.97 47.54 0 bottom
PC93  10u/10v_4  [C0402]  76.32 47.54 180 bottom
PC94  *2200p/50v_4  [C0402]  58.82 45.99 90 bottom
PC95  *10u/10v_4  [C0402]  76.4 46.06 180 bottom
PC96  *0.1u/10v_2  [C0201]  87.24 45.02 270 bottom
PC97  0.1u/10v_2  [C0201]  89.07 45.74 90 bottom
PC98  *0.1u/10v_2  [C0201]  89.78 45.74 270 bottom
PC99  0.1u/10v_2  [C0201]  65.75 45.38 90 bottom
PC100  *2200p/50v_4  [C0402]  51.27 40.21 270 bottom
PC101  1u/6.3v_2  [C0201]  66.49 42.87 180 bottom
PC102  2200p/50v_4  [C0402]  78.76 42.53 0 bottom
PC103  220u/2v_7343p_e4.5b_h1.1  [CC7343]  173.22 42.48 0 bottom
PC104  220u/2v_7343p_e4.5b_h1.1  [CC7343]  182.8 42.46 180 bottom
PC105  0.1u/25v_4  [C0402]  59.58 42.05 0 bottom
PC106  0.1u/25v_4  [C0402]  78.71 41.6 180 bottom
PC107  *2200p/50v_4  [C0402]  60.57 40.88 180 bottom
PC108  1u/6.3v_2  [C0201]  71.75 40.3 270 bottom
PC109  0.22u/25v_6x  [C0603]  54.68 39.42 0 bottom
PC110  0.22u/10v_4x  [C0402]  65.14 39.08 0 bottom
PC111  2200p/50v_4  [C0402]  174.59 38.17 0 bottom
PC112  0.1u/25v_4  [C0402]  64.56 37.62 90 top
PC113  10u/25v_6  [C0603]  61.82 37.96 270 bottom
PC114  10u/25v_6  [C0603]  63.19 37.96 270 bottom
PC115  2200p/50v_4  [C0402]  181.81 37.96 180 bottom
PC116  0.1u/10v_2  [C0201]  52.44 35.97 180 bottom
PC117  *0.1u/10v_2  [C0201]  78.23 34.86 90 bottom
PC118  0.1u/10v_2  [C0201]  78.94 34.86 270 bottom
PC119  *0.1u/10v_2  [C0201]  79.83 34.86 90 bottom
PC120  0.1u/25v_4  [C0402]  174.49 34.64 180 bottom
PC121  0.1u/25v_4  [C0402]  181.73 34.51 0 bottom
PC122  0.1u/10v_2  [C0201]  81.33 34.25 90 bottom
PC123  47u/6.3v_6  [C0603]  56.94 33.64 90 bottom
PC124  *47u/6.3v_6  [C0603]  55.47 33.64 90 bottom
PC125  22u/6.3v_6  [C0603]  162.05 32.79 180 bottom
PC126  0.1u/10v_2  [C0201]  77.13 32.63 270 bottom
PC127  22u/6.3v_6  [C0603]  74.85 31.59 90 bottom
PC128  *2200p/50v_4  [C0402]  163.91 31.43 180 bottom
PC129  *22u/6.3v_6  [C0603]  83.28 30.77 90 bottom
PC130  22u/6.3v_6  [C0603]  158.67 30.41 90 bottom
PC131  0.22u/25v_6x  [C0603]  173.81 30.24 90 bottom
PC132  0.22u/25v_6x  [C0603]  182.55 30.22 270 bottom
PC133  2.2u/10v_4  [C0402]  177.98 30.04 270 bottom
PC134  0.1u/10v_2  [C0201]  77.95 29.2 270 bottom
PC135  1000p/50v_2  [C0201]  78.76 29.2 270 bottom
PC136  1000p/50v_2  [C0201]  79.57 29.2 270 bottom
PC137  0.1u/10v_2  [C0201]  80.39 29.2 270 bottom
PC138  0.22u/25v_6x  [C0603]  163.63 28.98 0 bottom
PC139  1u/6.3v_2  [C0201]  172.05 28.54 180 bottom
PC140  0.1u/10v_2  [C0201]  184 28.15 0 bottom
PC141  0.01u/50v_4x  [C0402]  171.67 27.65 180 bottom
PC142  1000p/50v_2  [C0201]  185.5 27.47 90 bottom
PC143  1000p/50v_2  [C0201]  186.48 27.34 0 bottom
PC144  1000p/50v_2  [C0201]  183.89 27.24 270 bottom
PC145  0.1u/25v_4  [C0402]  66.44 27.17 270 bottom
PC146  0.1u/25v_4  [C0402]  67.53 27.17 270 bottom
PC147  0.1u/10v_2  [C0201]  172.08 26.79 180 bottom
PC148  1u/6.3v_2  [C0201]  164.51 26.45 90 bottom
PC149  0.01u/50v_4x  [C0402]  184.43 26.18 0 bottom
PC150  33p/50v_2  [C0201]  185.84 25.96 0 bottom
PC151  0.1u/25v_4  [C0402]  67.01 25.8 0 bottom
PC152  *2200p/50v_4  [C0402]  77.11 25.69 0 bottom
PC153  *0.1u/10v_2  [C0201]  158.45 25.5 180 bottom
PC154  0.01u/50v_4x  [C0402]  172.06 25.47 90 bottom
PC155  10u/10v_4  [C0402]  191.89 25.13 270 bottom
PC156  0.01u/50v_4x  [C0402]  170.66 25.06 0 bottom
PC157  1000p/50v_2  [C0201]  185.78 25.05 270 bottom
PC158  0.1u/10v_2  [C0201]  194.69 24.17 0 bottom
PC159  2.2u/10v_6x  [C0603]  72.14 23.75 180 bottom
PC160  *390p/50v_4  [C0402]  171.12 23.71 270 bottom
PC161  0.1u/25v_4  [C0402]  176.27 10.27 270 bottom
PC162  0.1u/25v_4  [C0402]  177.29 10.27 270 bottom
PC163  470p/50v_4x  [C0402]  172.07 23.71 90 bottom
PC164  6800p/50v_4x  [C0402]  184 23.69 90 bottom
PC165  *0.033u/10v_4x  [C0402]  185.09 23.69 90 bottom
PC166  0.1u/10v_2  [C0201]  189.33 23.66 180 bottom
PC167  10u/6.3v_6  [C0603]  179.06 10.27 180 bottom
PC168  0.1u/50v_6x  [C0603]  88.26 23.38 180 bottom
